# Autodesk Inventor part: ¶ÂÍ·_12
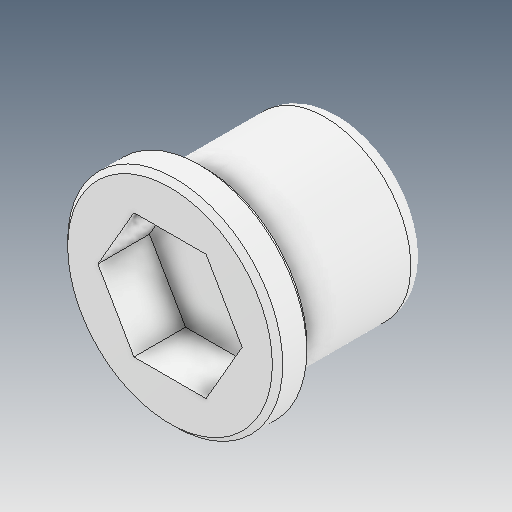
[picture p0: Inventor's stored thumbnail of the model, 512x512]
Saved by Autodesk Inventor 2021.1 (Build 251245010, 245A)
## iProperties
Created: 2021-06
Part Number: ¶ÂÍ·_12
Material: Ogólny
Document SubType Name: Modeling
Designer: user
Density: 1 g/cm^3
Appearance: Domyślna
Author: user
Revision Number: ÈÎºÎ
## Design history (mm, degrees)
feature "ÊäÈë1"
node "Bryła1"
